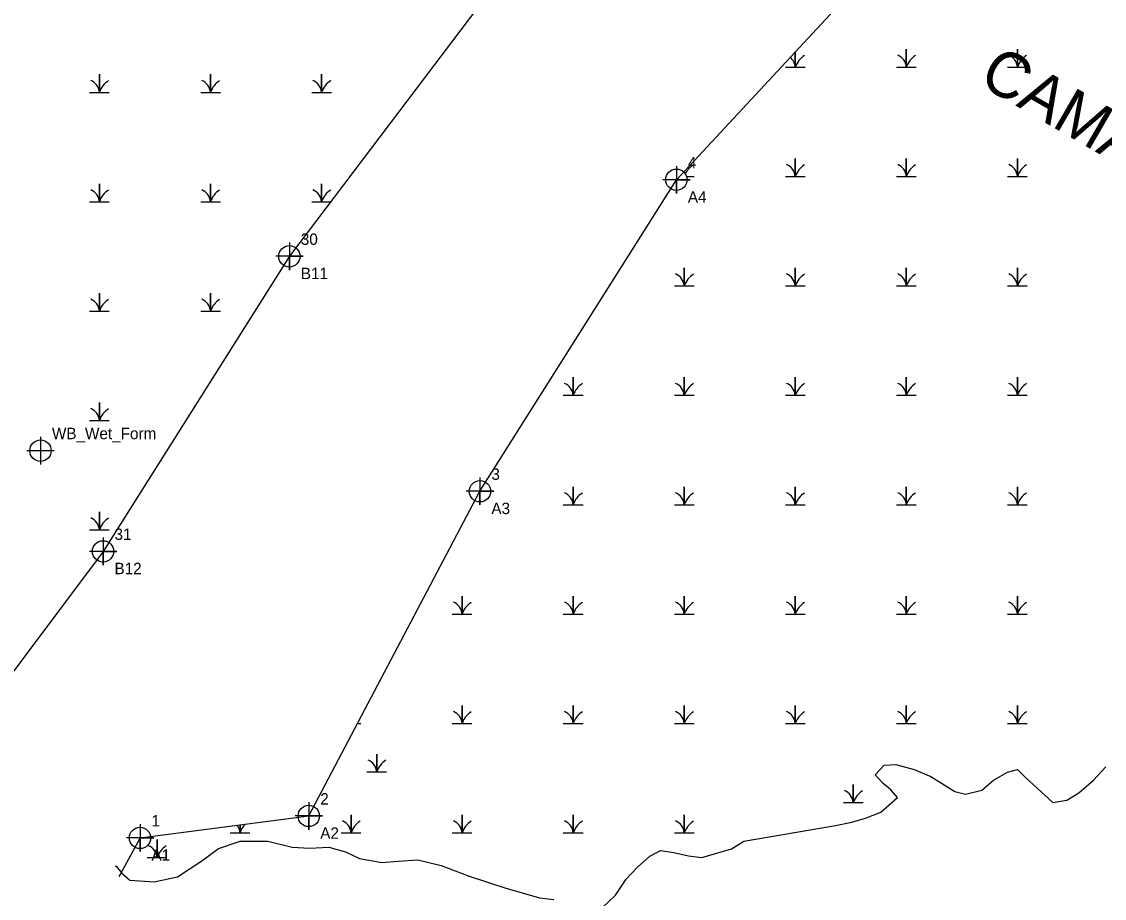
# Model space of a CAD drawing. Extents: x 2678633 to 2679425, y 623836 to 624637.
# Drawn here: x 2678971 to 2679208.1, y 624164.5 to 624356.4 of the extents above; entities that cross this region are included whole.
import ezdxf

# ---------------------------------------------------------------- set-up
doc = ezdxf.new("R2010")
doc.units = 0
for name, color, linetype in [('Cogo Default Point CELL', 7, 'Continuous'), ('COGO Default Point Number', 7, 'Continuous'), ('Exist Environmental Wetland Boundary', 7, 'Continuous'), ('Exist Environmental Wetland Boundary Cogo Comment', 7, 'Continuous'), ('Exist Environmental Wetland Boundary Cogo Number', 7, 'Continuous'), ('Exist Environmental Wetland Boundary Cogo Point CELL', 7, 'Continuous'), ('Exist Environmental Wetland Boundary Text', 7, 'Continuous'), ('Exist Hydro Jurisdictional Stream or Body of Water NEU Mitigable', 7, 'Continuous'), ('Exist Hydro Swamp or Marsh', 7, 'Continuous')]:
    doc.layers.add(name, color=color, linetype=linetype)

msp = doc.modelspace()

# ---------------------------------------------------------------- linework, layer by layer
at = {"layer": 'Cogo Default Point CELL'}
for points in [[(2678975.15, 624265.5), (2678975.15, 624262.5)], [(2678972.15, 624262.5), (2678975.15, 624262.5)], [(2678975.15, 624262.5), (2678978.15, 624262.5)], [(2678975.15, 624262.5), (2678975.15, 624259.5)]]:
    msp.add_lwpolyline(points, dxfattribs=at)
msp.add_circle((2678975.15, 624262.5), 2.34, dxfattribs=at)
at = {"layer": 'Exist Environmental Wetland Boundary'}
msp.add_line((2678996.94, 624177.71), (2678992.31, 624169.16), dxfattribs=at)
for points in [[(2679069.93, 624630.75), (2679087.52, 624604.07), (2679094.78, 624576.13), (2679101.43, 624567.27), (2679105.5, 624537.81), (2679136.33, 624529.73), (2679149.04, 624519.84), (2679171.39, 624510.69), (2679204.94, 624484.27), (2679140.71, 624428.23), (2679075.13, 624365.19), (2679029.64, 624305.05), (2678988.85, 624240.45), (2678945.79, 624182.95), (2678958.22, 624173.09)], [(2678996.94, 624177.71), (2679033.89, 624182.51), (2679071.36, 624253.6), (2679114.38, 624321.81), (2679163.39, 624374.56), (2679217.13, 624423.71), (2679286.14, 624470.62), (2679307.52, 624474.8), (2679321.51, 624489.84), (2679302.84, 624456.53), (2679292.78, 624438.21), (2679296.8, 624418.87), (2679319.66, 624396.04), (2679331.43, 624377.88), (2679317.29, 624347.71), (2679323.72, 624307.13), (2679356.11, 624275.91), (2679393.07, 624264.72), (2679417.04, 624216.21)]]:
    msp.add_lwpolyline(points, dxfattribs=at)
at = {"layer": 'Exist Environmental Wetland Boundary Cogo Point CELL'}
for points in [[(2679114.38, 624324.81), (2679114.38, 624318.81), (2679114.38, 624321.81), (2679117.38, 624321.81), (2679111.38, 624321.81)], [(2679029.64, 624308.05), (2679029.64, 624302.05), (2679029.64, 624305.05), (2679032.64, 624305.05), (2679026.64, 624305.05)], [(2679071.36, 624256.6), (2679071.36, 624250.6), (2679071.36, 624253.6), (2679074.36, 624253.6), (2679068.36, 624253.6)], [(2678988.85, 624243.45), (2678988.85, 624237.45), (2678988.85, 624240.45), (2678991.85, 624240.45), (2678985.85, 624240.45)], [(2679033.89, 624185.51), (2679033.89, 624179.51), (2679033.89, 624182.51), (2679036.89, 624182.51), (2679030.89, 624182.51)], [(2678996.94, 624180.71), (2678996.94, 624174.71), (2678996.94, 624177.71), (2678999.94, 624177.71), (2678993.94, 624177.71)]]:
    msp.add_lwpolyline(points, dxfattribs=at)
for centre in [(2679114.38, 624321.81), (2679029.64, 624305.05), (2679071.36, 624253.6), (2678988.85, 624240.45), (2679033.89, 624182.51), (2678996.94, 624177.71)]:
    msp.add_circle(centre, 2.34, dxfattribs=at)
at = {"layer": 'Exist Hydro Jurisdictional Stream or Body of Water NEU Mitigable'}
for points in [[(2679098.12, 624162.41), (2679101.05, 624165.19), (2679103.4, 624168.69), (2679105.88, 624171.31), (2679108.53, 624173.73), (2679110.9, 624174.98), (2679113.83, 624174.49), (2679116.98, 624173.76), (2679119.95, 624173.41), (2679126.41, 624175.34), (2679129.12, 624177.03), (2679149.21, 624180.46), (2679152.76, 624181.13), (2679155.76, 624182), (2679159.12, 624183.34), (2679162.78, 624186.56), (2679161.28, 624188.27), (2679159.61, 624189.63), (2679157.91, 624191.55), (2679159.82, 624193.66), (2679162.4, 624193.81), (2679166.39, 624192.72), (2679170.07, 624191.13), (2679175.35, 624187.86), (2679177.68, 624187.29), (2679181.25, 624188.17), (2679183.8, 624190.38), (2679186.87, 624192.12), (2679189.01, 624192.67), (2679190.78, 624190.95), (2679196.81, 624185.47), (2679199.83, 624186), (2679202.48, 624187.55), (2679205.68, 624190.38), (2679208.4, 624193.26)], [(2678991.46, 624171.5), (2678991.7, 624171.52), (2678992.92, 624170), (2678994.74, 624168.43), (2679000.05, 624168.08), (2679005.11, 624169.21), (2679010.44, 624172.67), (2679014.13, 624175.39), (2679018.83, 624176.98), (2679024.91, 624177.02), (2679030.21, 624175.65), (2679034.09, 624175.43), (2679038.3, 624175.67), (2679041.92, 624174.65), (2679045, 624173.19), (2679049.89, 624172.29), (2679053.44, 624172.63), (2679057.77, 624172.9), (2679062.88, 624171.65), (2679068.99, 624169.31), (2679076.78, 624166.77), (2679084.39, 624164.62), (2679087.52, 624164.2)]]:
    msp.add_lwpolyline(points, dxfattribs=at)
at = {"layer": 'Exist Hydro Swamp or Marsh'}
for p, q in [((2679048.75, 624193.92), (2679048.75, 624193.92)), ((2679153.08, 624187.23), (2679153.08, 624187.23)), ((2679000.66, 624175.17), (2679000.66, 624175.17))]:
    msp.add_line(p, q, dxfattribs=at)
for points in [[(2679138.24, 624346.47), (2679140.39, 624346.47), (2679140.39, 624349.8)], [(2679140.39, 624349.8), (2679140.39, 624346.47), (2679142.54, 624346.47)], [(2679162.55, 624346.47), (2679164.7, 624346.47), (2679164.7, 624350.41), (2679164.7, 624346.47), (2679166.85, 624346.47)], [(2679186.86, 624346.47), (2679189.01, 624346.47), (2679189.01, 624350.41), (2679189.01, 624346.47), (2679191.17, 624346.47)], [(2678985.9, 624340.95), (2678988.05, 624340.95), (2678988.05, 624344.9), (2678988.05, 624340.95), (2678990.2, 624340.95)], [(2679010.22, 624340.95), (2679012.37, 624340.95), (2679012.37, 624344.9), (2679012.37, 624340.95), (2679014.52, 624340.95)], [(2679034.53, 624340.95), (2679036.68, 624340.95), (2679036.68, 624344.9), (2679036.68, 624340.95), (2679038.83, 624340.95)], [(2679138.24, 624322.52), (2679140.39, 624322.52), (2679140.39, 624326.46), (2679140.39, 624322.52), (2679142.54, 624322.52)], [(2679162.55, 624322.52), (2679164.7, 624322.52), (2679164.7, 624326.46), (2679164.7, 624322.52), (2679166.85, 624322.52)], [(2679186.86, 624322.52), (2679189.01, 624322.52), (2679189.01, 624326.46), (2679189.01, 624322.52), (2679191.17, 624322.52)], [(2679116.08, 624323.39), (2679116.08, 624323.64)], [(2679116.08, 624323.64), (2679116.08, 624323.39)], [(2678985.9, 624317), (2678988.05, 624317), (2678988.05, 624320.95), (2678988.05, 624317), (2678990.2, 624317)], [(2679010.22, 624317), (2679012.37, 624317), (2679012.37, 624320.95), (2679012.37, 624317), (2679014.52, 624317)], [(2679034.53, 624317), (2679036.68, 624317), (2679036.68, 624320.95), (2679036.68, 624317), (2679038.68, 624317)], [(2679116.57, 624322.52), (2679118.23, 624322.52)], [(2679113.93, 624298.57), (2679116.08, 624298.57), (2679116.08, 624302.51), (2679116.08, 624298.57), (2679118.23, 624298.57)], [(2679138.24, 624298.57), (2679140.39, 624298.57), (2679140.39, 624302.51), (2679140.39, 624298.57), (2679142.54, 624298.57)], [(2679162.55, 624298.57), (2679164.7, 624298.57), (2679164.7, 624302.51), (2679164.7, 624298.57), (2679166.85, 624298.57)], [(2679186.86, 624298.57), (2679189.01, 624298.57), (2679189.01, 624302.51), (2679189.01, 624298.57), (2679191.17, 624298.57)], [(2678985.9, 624293.05), (2678988.05, 624293.05), (2678988.05, 624297), (2678988.05, 624293.05), (2678990.2, 624293.05)], [(2679010.22, 624293.05), (2679012.37, 624293.05), (2679012.37, 624297), (2679012.37, 624293.05), (2679014.52, 624293.05)], [(2679089.61, 624274.62), (2679091.76, 624274.62), (2679091.76, 624278.56), (2679091.76, 624274.62), (2679093.92, 624274.62)], [(2679113.93, 624274.62), (2679116.08, 624274.62), (2679116.08, 624278.56), (2679116.08, 624274.62), (2679118.23, 624274.62)], [(2679138.24, 624274.62), (2679140.39, 624274.62), (2679140.39, 624278.56), (2679140.39, 624274.62), (2679142.54, 624274.62)], [(2679162.55, 624274.62), (2679164.7, 624274.62), (2679164.7, 624278.56), (2679164.7, 624274.62), (2679166.85, 624274.62)], [(2679186.86, 624274.62), (2679189.01, 624274.62), (2679189.01, 624278.56), (2679189.01, 624274.62), (2679191.17, 624274.62)], [(2678985.9, 624269.1), (2678988.05, 624269.1), (2678988.05, 624273.05), (2678988.05, 624269.1), (2678990.2, 624269.1)], [(2679089.61, 624250.67), (2679091.76, 624250.67), (2679091.76, 624254.61), (2679091.76, 624250.67), (2679093.92, 624250.67)], [(2679113.93, 624250.67), (2679116.08, 624250.67), (2679116.08, 624254.61), (2679116.08, 624250.67), (2679118.23, 624250.67)], [(2679138.24, 624250.67), (2679140.39, 624250.67), (2679140.39, 624254.61), (2679140.39, 624250.67), (2679142.54, 624250.67)], [(2679162.55, 624250.67), (2679164.7, 624250.67), (2679164.7, 624254.61), (2679164.7, 624250.67), (2679166.85, 624250.67)], [(2679186.86, 624250.67), (2679189.01, 624250.67), (2679189.01, 624254.61), (2679189.01, 624250.67), (2679191.17, 624250.67)], [(2678985.9, 624245.15), (2678988.05, 624245.15), (2678988.05, 624249.1), (2678988.05, 624245.15), (2678990.2, 624245.15)], [(2679065.3, 624226.72), (2679067.45, 624226.72), (2679067.45, 624230.66), (2679067.45, 624226.72), (2679069.6, 624226.72)], [(2679089.61, 624226.72), (2679091.76, 624226.72), (2679091.76, 624230.66), (2679091.76, 624226.72), (2679093.92, 624226.72)], [(2679113.93, 624226.72), (2679116.08, 624226.72), (2679116.08, 624230.66), (2679116.08, 624226.72), (2679118.23, 624226.72)], [(2679138.24, 624226.72), (2679140.39, 624226.72), (2679140.39, 624230.66), (2679140.39, 624226.72), (2679142.54, 624226.72)], [(2679162.55, 624226.72), (2679164.7, 624226.72), (2679164.7, 624230.66), (2679164.7, 624226.72), (2679166.85, 624226.72)], [(2679186.86, 624226.72), (2679189.01, 624226.72), (2679189.01, 624230.66), (2679189.01, 624226.72), (2679191.17, 624226.72)], [(2679065.3, 624202.77), (2679067.45, 624202.77), (2679067.45, 624206.71), (2679067.45, 624202.77), (2679069.6, 624202.77)], [(2679089.61, 624202.77), (2679091.76, 624202.77), (2679091.76, 624206.71), (2679091.76, 624202.77), (2679093.92, 624202.77)], [(2679113.93, 624202.77), (2679116.08, 624202.77), (2679116.08, 624206.71), (2679116.08, 624202.77), (2679118.23, 624202.77)], [(2679138.24, 624202.77), (2679140.39, 624202.77), (2679140.39, 624206.71), (2679140.39, 624202.77), (2679142.54, 624202.77)], [(2679162.55, 624202.77), (2679164.7, 624202.77), (2679164.7, 624206.71), (2679164.7, 624202.77), (2679166.85, 624202.77)], [(2679186.86, 624202.77), (2679189.01, 624202.77), (2679189.01, 624206.71), (2679189.01, 624202.77), (2679191.17, 624202.77)], [(2679044.57, 624202.77), (2679045.29, 624202.77)], [(2679046.6, 624192.14), (2679048.75, 624192.14), (2679048.75, 624196.08), (2679048.75, 624192.14), (2679050.9, 624192.14)], [(2679150.93, 624185.44), (2679153.08, 624185.44), (2679153.08, 624189.39), (2679153.08, 624185.44), (2679155.23, 624185.44)], [(2679016.68, 624178.82), (2679018.83, 624178.82), (2679018.83, 624180.56)], [(2679018.83, 624180.56), (2679018.83, 624178.82), (2679020.98, 624178.82)], [(2679040.99, 624178.82), (2679043.14, 624178.82), (2679043.14, 624182.76), (2679043.14, 624178.82), (2679045.29, 624178.82)], [(2679065.3, 624178.82), (2679067.45, 624178.82), (2679067.45, 624182.76), (2679067.45, 624178.82), (2679069.6, 624178.82)], [(2679089.61, 624178.82), (2679091.76, 624178.82), (2679091.76, 624182.76), (2679091.76, 624178.82), (2679093.92, 624178.82)], [(2679113.93, 624178.82), (2679116.08, 624178.82), (2679116.08, 624182.76), (2679116.08, 624178.82), (2679118.23, 624178.82)], [(2678998.51, 624173.39), (2679000.66, 624173.39), (2679000.66, 624177.33), (2679000.66, 624173.39), (2679002.81, 624173.39)]]:
    msp.add_lwpolyline(points, dxfattribs=at)
for centre, radius, start, end in [((2679144.95, 624344.95), 4.81, 122.1274, 161.6222), ((2679161.64, 624346.25), 3.07, 4.1403, 67.535), ((2679169.26, 624344.95), 4.81, 122.1274, 161.6222), ((2679185.95, 624346.25), 3.07, 4.1403, 67.535), ((2679193.58, 624344.95), 4.81, 122.1274, 161.6222), ((2679137.32, 624346.25), 3.07, 4.1403, 50.3588), ((2678984.99, 624340.73), 3.07, 4.1403, 67.535), ((2678992.61, 624339.44), 4.81, 122.1274, 161.6222), ((2679009.3, 624340.73), 3.07, 4.1403, 67.535), ((2679016.93, 624339.44), 4.81, 122.1274, 161.6222), ((2679033.61, 624340.73), 3.07, 4.1403, 67.535), ((2679041.24, 624339.44), 4.81, 122.1274, 161.6222), ((2679137.32, 624322.3), 3.07, 4.1403, 67.535), ((2679161.64, 624322.3), 3.07, 4.1403, 67.535), ((2679185.95, 624322.3), 3.07, 4.1403, 67.535), ((2679120.64, 624321), 4.81, 122.1274, 154.4294), ((2679144.95, 624321), 4.81, 122.1274, 161.6222), ((2679169.26, 624321), 4.81, 122.1274, 161.6222), ((2679193.58, 624321), 4.81, 122.1274, 161.6222), ((2678984.99, 624316.78), 3.07, 4.1403, 67.535), ((2678992.61, 624315.49), 4.81, 122.1274, 161.6222), ((2679009.3, 624316.78), 3.07, 4.1403, 67.535), ((2679016.93, 624315.49), 4.81, 122.1274, 161.6222), ((2679033.61, 624316.78), 3.07, 4.1403, 67.535), ((2679041.24, 624315.49), 4.81, 122.1274, 161.6222), ((2679113.01, 624298.35), 3.07, 4.1403, 67.535), ((2679120.64, 624297.05), 4.81, 122.1274, 161.6222), ((2679137.32, 624298.35), 3.07, 4.1403, 67.535), ((2679144.95, 624297.05), 4.81, 122.1274, 161.6222), ((2679161.64, 624298.35), 3.07, 4.1403, 67.535), ((2679169.26, 624297.05), 4.81, 122.1274, 161.6222), ((2679185.95, 624298.35), 3.07, 4.1403, 67.535), ((2679193.58, 624297.05), 4.81, 122.1274, 161.6222), ((2678984.99, 624292.83), 3.07, 4.1403, 67.535), ((2678992.61, 624291.54), 4.81, 122.1274, 161.6222), ((2679009.3, 624292.83), 3.07, 4.1403, 67.535), ((2679016.93, 624291.54), 4.81, 122.1274, 161.6222), ((2679088.7, 624274.4), 3.07, 4.1403, 67.535), ((2679096.33, 624273.1), 4.81, 122.1274, 161.6222), ((2679113.01, 624274.4), 3.07, 4.1403, 67.535), ((2679120.64, 624273.1), 4.81, 122.1274, 161.6222), ((2679137.32, 624274.4), 3.07, 4.1403, 67.535), ((2679144.95, 624273.1), 4.81, 122.1274, 161.6222), ((2679161.64, 624274.4), 3.07, 4.1403, 67.535), ((2679169.26, 624273.1), 4.81, 122.1274, 161.6222), ((2679185.95, 624274.4), 3.07, 4.1403, 67.535), ((2679193.58, 624273.1), 4.81, 122.1274, 161.6222), ((2678984.99, 624268.88), 3.07, 4.1403, 67.535), ((2678992.61, 624267.59), 4.81, 122.1274, 161.6222), ((2679088.7, 624250.45), 3.07, 4.1403, 67.535), ((2679096.33, 624249.15), 4.81, 122.1274, 161.6222), ((2679113.01, 624250.45), 3.07, 4.1403, 67.535), ((2679120.64, 624249.15), 4.81, 122.1274, 161.6222), ((2679137.32, 624250.45), 3.07, 4.1403, 67.535), ((2679144.95, 624249.15), 4.81, 122.1274, 161.6222), ((2679161.64, 624250.45), 3.07, 4.1403, 67.535), ((2679169.26, 624249.15), 4.81, 122.1274, 161.6222), ((2679185.95, 624250.45), 3.07, 4.1403, 67.535), ((2679193.58, 624249.15), 4.81, 122.1274, 161.6222), ((2678984.99, 624244.93), 3.07, 4.1403, 67.535), ((2678992.61, 624243.64), 4.81, 122.1274, 161.6222), ((2679064.39, 624226.5), 3.07, 4.1403, 67.535), ((2679072.01, 624225.2), 4.81, 122.1274, 161.6222), ((2679088.7, 624226.5), 3.07, 4.1403, 67.535), ((2679096.33, 624225.2), 4.81, 122.1274, 161.6222), ((2679113.01, 624226.5), 3.07, 4.1403, 67.535), ((2679120.64, 624225.2), 4.81, 122.1274, 161.6222), ((2679137.32, 624226.5), 3.07, 4.1403, 67.535), ((2679144.95, 624225.2), 4.81, 122.1274, 161.6222), ((2679161.64, 624226.5), 3.07, 4.1403, 67.535), ((2679169.26, 624225.2), 4.81, 122.1274, 161.6222), ((2679185.95, 624226.5), 3.07, 4.1403, 67.535), ((2679193.58, 624225.2), 4.81, 122.1274, 161.6222), ((2679064.39, 624202.55), 3.07, 4.1403, 67.535), ((2679072.01, 624201.25), 4.81, 122.1274, 161.6222), ((2679088.7, 624202.55), 3.07, 4.1403, 67.535), ((2679096.33, 624201.25), 4.81, 122.1274, 161.6222), ((2679113.01, 624202.55), 3.07, 4.1403, 67.535), ((2679120.64, 624201.25), 4.81, 122.1274, 161.6222), ((2679137.32, 624202.55), 3.07, 4.1403, 67.535), ((2679144.95, 624201.25), 4.81, 122.1274, 161.6222), ((2679161.64, 624202.55), 3.07, 4.1403, 67.535), ((2679169.26, 624201.25), 4.81, 122.1274, 161.6222), ((2679185.95, 624202.55), 3.07, 4.1403, 67.535), ((2679193.58, 624201.25), 4.81, 122.1274, 161.6222), ((2679045.68, 624191.92), 3.07, 4.1403, 67.535), ((2679053.31, 624190.62), 4.81, 122.1274, 161.6222), ((2679150.02, 624185.22), 3.07, 4.1403, 67.535), ((2679157.64, 624183.93), 4.81, 122.1274, 161.6222), ((2679023.39, 624177.3), 4.81, 134.9163, 161.6222), ((2679040.07, 624178.6), 3.07, 4.1403, 67.535), ((2679047.7, 624177.3), 4.81, 122.1274, 161.6222), ((2679064.39, 624178.6), 3.07, 4.1403, 67.535), ((2679072.01, 624177.3), 4.81, 122.1274, 161.6222), ((2679088.7, 624178.6), 3.07, 4.1403, 67.535), ((2679096.33, 624177.3), 4.81, 122.1274, 161.6222), ((2679113.01, 624178.6), 3.07, 4.1403, 67.535), ((2679120.64, 624177.3), 4.81, 122.1274, 161.6222), ((2679015.76, 624178.6), 3.07, 4.1403, 37.6127), ((2678997.6, 624173.17), 3.07, 4.1403, 67.535), ((2679005.22, 624171.87), 4.81, 122.1274, 161.6222)]:
    msp.add_arc(centre, radius, start, end, dxfattribs=at)

# ---------------------------------------------------------------- texts
at = {"layer": 'COGO Default Point Number'}
msp.add_text('WB_Wet_Form', height=2.5, dxfattribs=at).set_placement((2678977.65, 624265.01))
at = {"layer": 'Exist Environmental Wetland Boundary Cogo Comment'}
for s, p in [('A4', (2679116.88, 624316.81)), ('B11', (2679032.14, 624300.05)), ('A3', (2679073.86, 624248.6)), ('B12', (2678991.35, 624235.45)), ('A2', (2679036.39, 624177.51)), ('A1', (2678999.44, 624172.71))]:
    msp.add_text(s, height=2.5, dxfattribs=at).set_placement(p)
at = {"layer": 'Exist Environmental Wetland Boundary Cogo Number'}
for s, p in [('4', (2679116.88, 624324.31)), ('30', (2679032.14, 624307.55)), ('3', (2679073.86, 624256.1)), ('31', (2678991.35, 624242.95)), ('2', (2679036.39, 624185.01)), ('1', (2678999.44, 624180.21))]:
    msp.add_text(s, height=2.5, dxfattribs=at).set_placement(p)
at = {"layer": 'Exist Environmental Wetland Boundary Text'}
msp.add_text('CAMA wetland', height=10, rotation=330, dxfattribs=at).set_placement((2679180.16, 624342.91))

doc.saveas('drawing.dxf')
